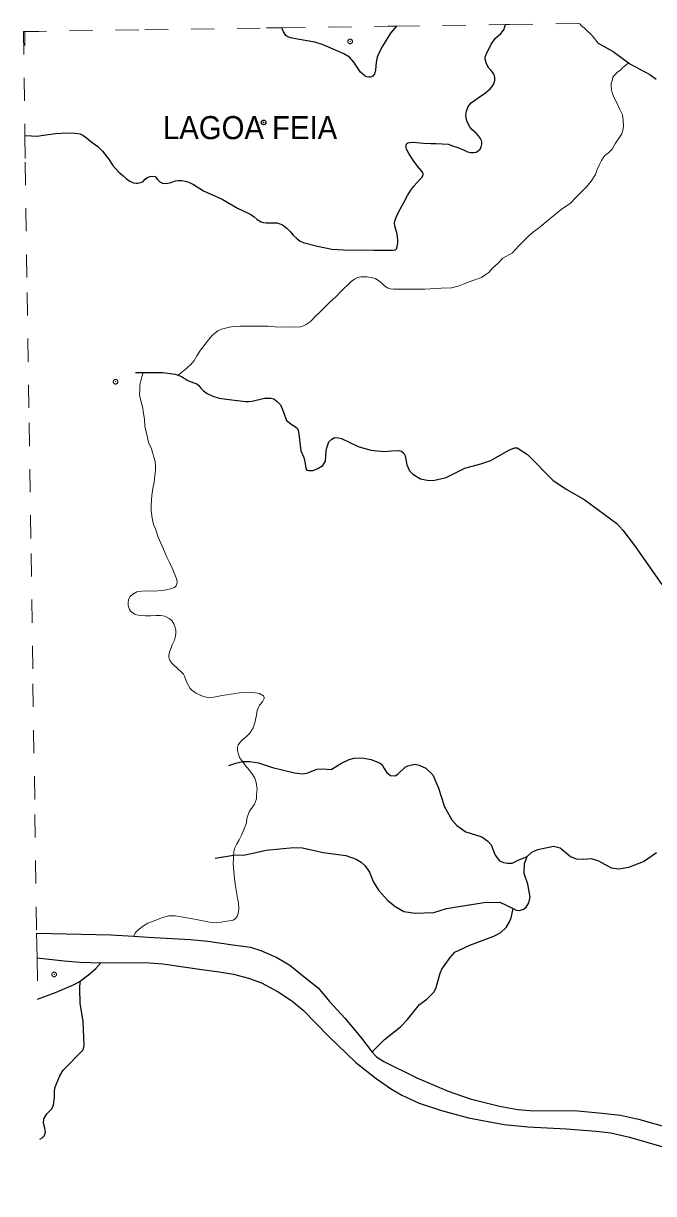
# Model space of a CAD drawing. Extents: x 267.7 to 296, y 7537.7 to 7565.8.
# Drawn here: x 267.7 to 270.43, y 7560.4 to 7565.47 of the extents above; entities that cross this region are included whole.
import ezdxf
from ezdxf.enums import TextEntityAlignment as Align

# ---------------------------------------------------------------- set-up
doc = ezdxf.new("R2010")
doc.units = 0
doc.header["$LTSCALE"] = 0.04
doc.header["$PDMODE"] = 32
doc.header["$PDSIZE"] = 0.02
doc.linetypes.add('SHORT_DASHED', pattern=[2.7, 1.5, -1.2])
for name, color, linetype, lineweight in [('1', 7, 'Continuous', 25), ('2', 7, 'Continuous', 25), ('21', 7, 'SHORT_DASHED', 13), ('62', 7, 'SHORT_DASHED', 13), ('63', 7, 'Continuous', 13), ('7', 7, 'Continuous', 25)]:
    doc.layers.add(name, color=color, linetype=linetype, lineweight=lineweight)
doc.layers.add('61', color=7, linetype='Continuous')

msp = doc.modelspace()

# ---------------------------------------------------------------- linework, layer by layer
at = {"layer": '1'}
for points in [[(267.7577, 7561.5276), (268.0791, 7561.5208), (268.1794, 7561.5143)], [(268.1794, 7561.5143), (268.2414, 7561.5102), (268.4249, 7561.4996), (268.5002, 7561.4928), (268.6084, 7561.4764), (268.6847, 7561.4667), (268.7301, 7561.4523), (268.7987, 7561.4223), (268.8557, 7561.3885), (268.9252, 7561.3325), (268.9784, 7561.2909), (269.0276, 7561.2311), (269.0952, 7561.1586), (269.1657, 7561.0727), (269.2121, 7561.0128)], [(267.7593, 7561.4209), (267.8767, 7561.4075), (267.9457, 7561.4017), (268.0364, 7561.3992)], [(268.0364, 7561.3992), (268.227, 7561.4), (268.3044, 7561.395), (268.4741, 7561.3709), (268.5489, 7561.3596), (268.6114, 7561.3501), (268.6763, 7561.3326), (268.7329, 7561.3118), (268.8045, 7561.2735), (268.8636, 7561.2344), (268.9126, 7561.1937), (269.0225, 7561.0813), (269.1415, 7560.9682), (269.2297, 7560.8983), (269.2921, 7560.855), (269.3404, 7560.8267), (269.4161, 7560.7917), (269.5134, 7560.7601), (269.6291, 7560.7285), (269.7847, 7560.6985), (269.8871, 7560.6894), (270.0543, 7560.6802), (270.1825, 7560.6694), (270.2474, 7560.6636), (270.3281, 7560.6436), (270.6385, 7560.5546)], [(269.2121, 7561.0128), (269.2305, 7560.9925), (269.2633, 7560.9712), (269.4053, 7560.9017), (269.5415, 7560.8437), (269.6371, 7560.8099), (269.7646, 7560.778), (269.8438, 7560.7636), (269.9134, 7560.7578), (270.0882, 7560.7597), (270.2099, 7560.7481), (270.2891, 7560.7394), (270.3664, 7560.722), (270.5103, 7560.6815), (270.9372, 7560.5636), (271.1913, 7560.4931), (271.4501, 7560.4207), (271.787, 7560.3318)]]:
    msp.add_lwpolyline(points, dxfattribs=at)
at = {"layer": '2'}
for points in [[(269.3177, 7565.456), (269.2917, 7565.4246), (269.2794, 7565.4072), (269.257, 7565.3684), (269.2417, 7565.3388), (269.2345, 7565.321), (269.2315, 7565.3072), (269.2284, 7565.2847), (269.2264, 7565.2643), (269.2218, 7565.2485), (269.2156, 7565.2393), (269.2085, 7565.2362), (269.2039, 7565.2342), (269.1978, 7565.2342), (269.1886, 7565.2367), (269.1825, 7565.2398), (269.162, 7565.2566), (269.1442, 7565.2827), (269.1329, 7565.3), (269.1136, 7565.321), (269.0891, 7565.3363), (269.0436, 7565.3567), (269.0002, 7565.3751), (268.9635, 7565.3863), (268.8885, 7565.3991), (268.8583, 7565.4057), (268.8466, 7565.4093), (268.8374, 7565.4159), (268.8272, 7565.4312), (268.8231, 7565.4414), (268.8221, 7565.4488)], [(269.3601, 7564.9361), (269.3601, 7564.9422), (269.3631, 7564.9468), (269.3672, 7564.9504), (269.3734, 7564.9524), (269.3897, 7564.9529), (269.4341, 7564.9489), (269.4663, 7564.9468), (269.4897, 7564.9478), (269.5423, 7564.9443), (269.5607, 7564.9381), (269.5831, 7564.93), (269.6112, 7564.9182), (269.626, 7564.9111), (269.6403, 7564.9085), (269.6531, 7564.9085), (269.6633, 7564.9101), (269.672, 7564.9157), (269.6801, 7564.9233), (269.6847, 7564.9336), (269.6878, 7564.9443), (269.6878, 7564.9545), (269.6857, 7564.9611), (269.6817, 7564.9698), (269.6725, 7564.9805), (269.6628, 7564.9917), (269.6444, 7565.0081), (269.6352, 7565.0198), (269.6245, 7565.0418), (269.6194, 7565.0566), (269.6178, 7565.0709), (269.6204, 7565.0872), (269.6286, 7565.1076), (269.6418, 7565.1234), (269.6714, 7565.1454), (269.7031, 7565.1668), (269.724, 7565.1847), (269.7327, 7565.1949), (269.7393, 7565.2061), (269.7434, 7565.2209), (269.7434, 7565.2316), (269.7424, 7565.2413), (269.7393, 7565.248), (269.7347, 7565.2556), (269.7281, 7565.2633), (269.7184, 7565.274), (269.7082, 7565.2919), (269.7046, 7565.3021), (269.7021, 7565.3133), (269.7026, 7565.321), (269.7067, 7565.3332), (269.7281, 7565.3771), (269.7465, 7565.4031), (269.7577, 7565.4144), (269.7694, 7565.4236), (269.7776, 7565.4327), (269.7837, 7565.443), (269.7863, 7565.4491), (269.7898, 7565.4629)], [(267.7068, 7564.9825), (267.7349, 7564.98), (267.7614, 7564.979), (267.7773, 7564.9815), (267.8401, 7564.9907), (267.8896, 7564.9938), (267.9243, 7564.9923), (267.9457, 7564.9892), (267.9544, 7564.9856), (267.9666, 7564.978), (267.9983, 7564.9519), (268.0228, 7564.9341), (268.0427, 7564.9136), (268.0697, 7564.8805), (268.0881, 7564.8529), (268.1121, 7564.8253), (268.1325, 7564.8075), (268.1468, 7564.7947), (268.1621, 7564.7845), (268.178, 7564.7774), (268.1897, 7564.7753), (268.1968, 7564.7753), (268.2091, 7564.7784), (268.2198, 7564.7835), (268.228, 7564.7927), (268.2372, 7564.7998), (268.2494, 7564.8044), (268.2627, 7564.8059), (268.2714, 7564.8039), (268.276, 7564.7993), (268.2821, 7564.7917), (268.2913, 7564.782), (268.3035, 7564.7758), (268.3158, 7564.7743), (268.327, 7564.7753), (268.3357, 7564.7774), (268.3438, 7564.7804), (268.3602, 7564.7855), (268.3719, 7564.7871), (268.3867, 7564.7866), (268.402, 7564.7845), (268.4168, 7564.7794), (268.4372, 7564.7702), (268.4817, 7564.7427), (268.5613, 7564.7059), (268.6281, 7564.6681), (268.6746, 7564.6462), (268.6858, 7564.6395), (268.7006, 7564.6293), (268.7134, 7564.6186), (268.7312, 7564.6079), (268.7409, 7564.6054), (268.7527, 7564.6038), (268.767, 7564.6038), (268.7996, 7564.6033), (268.8119, 7564.5997), (268.8231, 7564.5946), (268.8441, 7564.5788), (268.8578, 7564.5645), (268.8696, 7564.5512), (268.8869, 7564.5349), (268.9002, 7564.5252), (268.9135, 7564.5186), (268.9747, 7564.5028), (269.038, 7564.49), (269.088, 7564.4869), (269.2187, 7564.4859), (269.3029, 7564.4854), (269.3116, 7564.4864), (269.3152, 7564.488), (269.3177, 7564.492), (269.3203, 7564.5012), (269.3233, 7564.5155), (269.3233, 7564.5267), (269.3213, 7564.5451), (269.3187, 7564.5615), (269.3141, 7564.5757), (269.3101, 7564.5911), (269.309, 7564.6028), (269.3111, 7564.6105), (269.3152, 7564.6242), (269.3259, 7564.6503), (269.3494, 7564.6916), (269.3647, 7564.7222), (269.3795, 7564.7452), (269.3933, 7564.7631), (269.407, 7564.7784), (269.4203, 7564.7927), (269.4285, 7564.8019), (269.4321, 7564.8085), (269.4336, 7564.8131), (269.4336, 7564.8172), (269.4321, 7564.8202), (269.428, 7564.8274), (269.4091, 7564.8498)], [(269.4091, 7564.8498), (269.3892, 7564.8754), (269.3708, 7564.9039), (269.3616, 7564.9233), (269.3601, 7564.929), (269.3601, 7564.9361)]]:
    msp.add_lwpolyline(points, dxfattribs=at)
msp.add_point((268.7416, 7565.039), dxfattribs=at)
at = {"layer": '21'}
for points in [[(270.1922, 7565.3823), (270.1707, 7565.4091), (270.1597, 7565.4214), (270.1422, 7565.4362), (270.1306, 7565.4479), (270.1189, 7565.4569), (270.1112, 7565.4676)], [(270.2638, 7565.2442), (270.2767, 7565.2572), (270.289, 7565.2656), (270.2993, 7565.2766), (270.311, 7565.2856), (270.3235, 7565.2968)], [(268.3718, 7563.9436), (268.4005, 7563.9673), (268.4257, 7563.99), (268.4412, 7564.0081), (268.4528, 7564.0281), (268.4683, 7564.0527), (268.502, 7564.0966), (268.5175, 7564.1141), (268.5298, 7564.1257), (268.5433, 7564.1361), (268.5589, 7564.1438), (268.588, 7564.1509), (268.6086, 7564.1548), (268.6416, 7564.1561), (268.7037, 7564.1568), (268.7632, 7564.1561), (268.7916, 7564.1542), (268.8795, 7564.1522), (268.9015, 7564.1542), (268.9145, 7564.1574), (268.9261, 7564.1639), (268.9429, 7564.1749), (268.9532, 7564.1852), (268.9681, 7564.2007), (268.9817, 7564.2137), (268.9869, 7564.2188), (269.0289, 7564.2602), (269.056, 7564.2848), (269.0748, 7564.3048), (269.0877, 7564.3184), (269.1071, 7564.3352), (269.1213, 7564.3494), (269.1356, 7564.3604), (269.1485, 7564.3669), (269.1627, 7564.3701), (269.1905, 7564.3701), (269.2267, 7564.3624), (269.2416, 7564.3533), (269.2513, 7564.3449), (269.2668, 7564.3294), (269.281, 7564.3216), (269.2907, 7564.3184), (269.305, 7564.3171), (269.3651, 7564.3165), (269.4401, 7564.3165), (269.5112, 7564.321), (269.5565, 7564.3229), (269.5849, 7564.33), (269.6069, 7564.3378), (269.6437, 7564.3533), (269.6864, 7564.3675), (269.7052, 7564.3798), (269.7174, 7564.3895), (269.7336, 7564.407), (269.7562, 7564.4283), (269.7789, 7564.4516), (269.8209, 7564.4736), (269.8468, 7564.5027), (269.87, 7564.5266), (269.8914, 7564.5479), (269.9114, 7564.5647), (269.9315, 7564.5789), (269.9664, 7564.608), (269.9987, 7564.6339), (270.031, 7564.6623), (270.0724, 7564.6889), (270.0963, 7564.7154), (270.1209, 7564.7393), (270.1409, 7564.7593), (270.161, 7564.7845), (270.1804, 7564.8136), (270.1881, 7564.835), (270.1972, 7564.857), (270.2062, 7564.8744), (270.2133, 7564.886), (270.2224, 7564.8964), (270.2353, 7564.9061), (270.2521, 7564.9235), (270.2676, 7564.9488), (270.2799, 7564.9675), (270.2942, 7564.9895), (270.2993, 7565.0044), (270.3013, 7565.0231), (270.3, 7565.047), (270.2974, 7565.0723), (270.2864, 7565.0942), (270.2748, 7565.1214), (270.2625, 7565.1421), (270.2541, 7565.1628), (270.2495, 7565.1796), (270.2489, 7565.2003), (270.2489, 7565.2087), (270.2521, 7565.2184), (270.256, 7565.2345), (270.2638, 7565.2442)], [(268.2724, 7563.5322), (268.2731, 7563.5516), (268.2712, 7563.571), (268.266, 7563.5891), (268.2628, 7563.6001), (268.2556, 7563.6247), (268.2427, 7563.6531), (268.2388, 7563.6738), (268.2265, 7563.7229), (268.2253, 7563.7533), (268.2214, 7563.7785), (268.2175, 7563.8012), (268.2097, 7563.8335), (268.2039, 7563.8594), (268.2046, 7563.8788), (268.2052, 7563.8994), (268.2059, 7563.9085), (268.2136, 7563.9363), (268.2188, 7563.9557)], [(268.2556, 7563.4042), (268.2576, 7563.4236), (268.2608, 7563.4533), (268.2666, 7563.4805), (268.2699, 7563.5096), (268.2724, 7563.5322)], [(268.65, 7562.2712), (268.6377, 7562.2889), (268.6306, 7562.307), (268.6287, 7562.3193), (268.6287, 7562.3316), (268.6319, 7562.3432), (268.6416, 7562.3562), (268.6539, 7562.3691), (268.6681, 7562.3794), (268.6817, 7562.3937), (268.6959, 7562.4163), (268.7037, 7562.4383), (268.7114, 7562.4712), (268.714, 7562.4926), (268.7237, 7562.5152), (268.7367, 7562.5288), (268.7444, 7562.5437), (268.7444, 7562.5482), (268.7412, 7562.5559), (268.7237, 7562.565), (268.7147, 7562.5676), (268.694, 7562.5702), (268.6642, 7562.5708), (268.6364, 7562.5682), (268.5621, 7562.5566), (268.5265, 7562.5501), (268.5065, 7562.5475), (268.4865, 7562.5514), (268.469, 7562.5566), (268.449, 7562.5669), (268.438, 7562.574), (268.4296, 7562.5818), (268.4237, 7562.587), (268.4095, 7562.6109), (268.405, 7562.6245), (268.3985, 7562.6406), (268.394, 7562.649), (268.3869, 7562.6568), (268.3675, 7562.6749), (268.3526, 7562.6878), (268.3423, 7562.6988), (268.3352, 7562.7092), (268.33, 7562.7208), (268.33, 7562.7324), (268.3352, 7562.7493), (268.3403, 7562.7635), (268.3455, 7562.7758), (268.3546, 7562.7971), (268.3591, 7562.8139), (268.361, 7562.8262), (268.3617, 7562.8398), (268.3584, 7562.8514), (268.3526, 7562.8676), (268.3442, 7562.8812), (268.3319, 7562.8908), (268.3132, 7562.8999), (268.2951, 7562.9031), (268.2744, 7562.9038), (268.2518, 7562.9025), (268.2291, 7562.9025), (268.2123, 7562.9038), (268.1981, 7562.9051), (268.1852, 7562.9077), (268.1768, 7562.9128), (268.1645, 7562.9219), (268.1606, 7562.9296), (268.1548, 7562.9471), (268.1548, 7562.9581), (268.1561, 7562.9723), (268.1638, 7562.9859), (268.1742, 7562.9956), (268.1923, 7563.0053), (268.2136, 7563.0092), (268.2362, 7563.0098), (268.2653, 7563.0092), (268.3015, 7563.0118), (268.3203, 7563.015), (268.3377, 7563.0189), (268.3546, 7563.0247), (268.3623, 7563.0324), (268.3675, 7563.0454), (268.3655, 7563.0596), (268.3571, 7563.0809), (268.3455, 7563.1081), (268.3339, 7563.1327), (268.3222, 7563.1566), (268.308, 7563.1908), (268.2847, 7563.2419), (268.2724, 7563.2794), (268.264, 7563.2975), (268.2582, 7563.3253), (268.255, 7563.346), (268.2543, 7563.3583), (268.2537, 7563.3796), (268.2556, 7563.4042)], [(268.6115, 7561.8651), (268.6125, 7561.8797), (268.6171, 7561.8971), (268.6248, 7561.9152), (268.6352, 7561.932), (268.6461, 7561.9521), (268.6578, 7561.9799), (268.6675, 7562.0057), (268.6694, 7562.0245), (268.6746, 7562.0413), (268.6804, 7562.0555), (268.692, 7562.0717), (268.7024, 7562.0859), (268.7102, 7562.1092), (268.7114, 7562.1279), (268.7134, 7562.1506), (268.7089, 7562.1803), (268.7037, 7562.1991), (268.6946, 7562.2139), (268.6804, 7562.2314), (268.6727, 7562.2424), (268.6642, 7562.2514), (268.65, 7562.2712)], [(268.1794, 7561.5143), (268.1865, 7561.5312), (268.202, 7561.5454), (268.2214, 7561.5596), (268.2401, 7561.5713), (268.255, 7561.5771), (268.2789, 7561.5855), (268.2996, 7561.5933), (268.3145, 7561.5984), (268.3306, 7561.6023), (268.3591, 7561.6023), (268.3752, 7561.6004), (268.4173, 7561.5926), (268.4496, 7561.5868), (268.5143, 7561.5745), (268.5356, 7561.5719), (268.5582, 7561.5752), (268.5724, 7561.5777), (268.6099, 7561.5836), (268.6196, 7561.5907), (268.6274, 7561.6004), (268.6319, 7561.6127), (268.6339, 7561.6327), (268.6332, 7561.6586), (268.628, 7561.6786), (268.6242, 7561.7045), (268.6196, 7561.731), (268.6158, 7561.7639), (268.6119, 7561.795), (268.6099, 7561.8273), (268.6106, 7561.8512), (268.6115, 7561.8651)]]:
    msp.add_lwpolyline(points, dxfattribs=at)
for p in [(269.1168, 7565.3895), (268.0998, 7563.9157), (267.8337, 7561.3487)]:
    msp.add_point(p, dxfattribs=at)
at = {"layer": '62'}
for p, q in [((269.3177, 7565.456), (269.7898, 7565.4629)), ((267.7002, 7565.4324), (267.7068, 7564.9825)), ((267.7593, 7561.4209), (267.762, 7561.2411))]:
    msp.add_line(p, q, dxfattribs=at)
for points in [[(267.7002, 7565.4324), (268.2272, 7565.4401), (268.7541, 7565.4478), (268.8221, 7565.4488)], [(268.8221, 7565.4488), (269.2811, 7565.4555), (269.2887, 7565.4556), (269.3177, 7565.456)], [(269.7898, 7565.4629), (269.808, 7565.4632), (270.1112, 7565.4676)], [(267.7068, 7564.9825), (267.7085, 7564.8673), (267.7168, 7564.3023), (267.7252, 7563.7372), (267.7335, 7563.1722), (267.7418, 7562.6071), (267.7501, 7562.0421), (267.7577, 7561.5276)], [(267.7577, 7561.5276), (267.7585, 7561.477), (267.7593, 7561.4209)]]:
    msp.add_lwpolyline(points, dxfattribs=at)
at = {"layer": '63'}
msp.add_lwpolyline([(267.7674, 7565.432), (267.7058, 7565.432), (267.7058, 7565.3713)], dxfattribs=at)
at = {"layer": '7'}
for p, q in [((268.1859, 7563.9557), (268.2188, 7563.9557)), ((268.532, 7561.8531), (268.6115, 7561.8651))]:
    msp.add_line(p, q, dxfattribs=at)
for points in [[(270.1922, 7565.3823), (270.2571, 7565.3453), (270.3235, 7565.2968)], [(270.3235, 7565.2968), (270.3293, 7565.2926), (270.4159, 7565.2456), (270.4429, 7565.2259)], [(268.2188, 7563.9557), (268.3042, 7563.9557), (268.3585, 7563.9484), (268.3718, 7563.9436)], [(268.3718, 7563.9436), (268.3852, 7563.9389), (268.4127, 7563.9213), (268.4395, 7563.911), (268.4517, 7563.9066), (268.461, 7563.8994), (268.4692, 7563.8882), (268.4815, 7563.8769), (268.4969, 7563.8654), (268.5213, 7563.8526), (268.5484, 7563.8448), (268.5808, 7563.8407), (268.6625, 7563.8305), (268.6765, 7563.8307), (268.692, 7563.8321), (268.7459, 7563.844), (268.773, 7563.8448), (268.7855, 7563.8417), (268.8001, 7563.8296), (268.8141, 7563.8153), (268.8239, 7563.7949), (268.8415, 7563.7478), (268.8653, 7563.7294), (268.8797, 7563.7209), (268.8887, 7563.7139), (268.889, 7563.7137), (268.8926, 7563.7002), (268.9023, 7563.6162), (268.9153, 7563.5876), (268.9222, 7563.5615), (268.9239, 7563.5402), (268.929, 7563.533), (268.9383, 7563.531), (268.9547, 7563.532), (268.9737, 7563.5383), (268.9989, 7563.553), (269.0092, 7563.5723), (269.0124, 7563.617), (269.0161, 7563.6293), (269.0238, 7563.6553), (269.0368, 7563.6675), (269.0491, 7563.6747), (269.0659, 7563.6731), (269.0789, 7563.6695), (269.1515, 7563.6358), (269.2067, 7563.6191), (269.2635, 7563.6143), (269.2962, 7563.6161), (269.3295, 7563.618), (269.3396, 7563.6151), (269.3498, 7563.6069), (269.355, 7563.5946), (269.3622, 7563.5556), (269.3734, 7563.5302), (269.3886, 7563.515), (269.4216, 7563.4959), (269.4507, 7563.4889), (269.4772, 7563.4882), (269.5323, 7563.5008), (269.6141, 7563.5408), (269.6836, 7563.5607), (269.727, 7563.575), (269.8044, 7563.62), (269.8295, 7563.6293), (269.8407, 7563.6297), (269.8851, 7563.6009), (269.9952, 7563.49), (270.0537, 7563.4512), (270.1268, 7563.4082), (270.1356, 7563.403), (270.2724, 7563.3014), (270.299, 7563.2723), (270.3497, 7563.2064), (270.4684, 7563.0369)], [(268.5903, 7562.2535), (268.6211, 7562.2633), (268.65, 7562.2712)], [(268.65, 7562.2712), (268.6824, 7562.2712), (268.72, 7562.2657), (268.7794, 7562.2445), (268.8751, 7562.2214), (268.9122, 7562.217), (268.9326, 7562.2215), (268.9719, 7562.2373), (268.9968, 7562.24), (269.0344, 7562.2362), (269.0792, 7562.264), (269.1126, 7562.2799), (269.1347, 7562.286), (269.1708, 7562.2872), (269.1835, 7562.2846), (269.2079, 7562.2795), (269.2467, 7562.2634), (269.255, 7562.2568), (269.264, 7562.2406), (269.2749, 7562.2254), (269.2913, 7562.2106), (269.3121, 7562.2083), (269.3239, 7562.2156), (269.3548, 7562.2459), (269.3668, 7562.2529), (269.3978, 7562.2591), (269.4152, 7562.2551), (269.4449, 7562.2425), (269.4746, 7562.2126), (269.5006, 7562.1527), (269.5072, 7562.1325), (269.5259, 7562.0749), (269.558, 7562.0187), (269.5785, 7561.9933), (269.6187, 7561.9665), (269.6875, 7561.9441), (269.7133, 7561.9263), (269.7277, 7561.91), (269.7456, 7561.8655), (269.7637, 7561.841), (269.7809, 7561.8333), (269.7994, 7561.8302), (269.8189, 7561.8312), (269.8456, 7561.8435), (269.8839, 7561.8603)], [(268.6115, 7561.8651), (268.6214, 7561.8666), (268.6555, 7561.8647), (268.752, 7561.8866), (268.8712, 7561.8987), (268.9095, 7561.8977), (268.9807, 7561.8811), (268.9992, 7561.8768), (269.0983, 7561.8636), (269.1433, 7561.8483), (269.1643, 7561.8353), (269.1816, 7561.8188), (269.2001, 7561.7913), (269.2166, 7561.7519), (269.239, 7561.7145), (269.278, 7561.6704), (269.3118, 7561.6437), (269.3182, 7561.64), (269.3497, 7561.6215), (269.399, 7561.6146), (269.4797, 7561.6169), (269.5341, 7561.6347), (269.6967, 7561.6608), (269.7649, 7561.6614), (269.8228, 7561.6343)], [(269.8839, 7561.8603), (269.904, 7561.8777), (269.9305, 7561.8894), (269.9987, 7561.9049), (270.0274, 7561.8978), (270.0715, 7561.86), (270.0971, 7561.8497), (270.1303, 7561.8475), (270.1615, 7561.8514), (270.1937, 7561.8402), (270.2488, 7561.8102), (270.2817, 7561.8062), (270.3244, 7561.8137), (270.3884, 7561.8381), (270.445, 7561.8765)], [(269.8228, 7561.6343), (269.837, 7561.6276), (269.8507, 7561.6259), (269.8681, 7561.6315), (269.8793, 7561.6404), (269.8915, 7561.6585), (269.8965, 7561.6831), (269.887, 7561.7403), (269.8711, 7561.7859), (269.8723, 7561.8292), (269.8795, 7561.8487), (269.8839, 7561.8603)], [(269.2121, 7561.0128), (269.2256, 7561.0273), (269.2658, 7561.0668), (269.3343, 7561.1224), (269.3649, 7561.1539), (269.4174, 7561.2191), (269.4496, 7561.2424), (269.4803, 7561.274), (269.4889, 7561.2925), (269.5063, 7561.3538), (269.5147, 7561.3711), (269.5504, 7561.4223), (269.5708, 7561.4449), (269.6352, 7561.475), (269.7394, 7561.5144), (269.7703, 7561.5305), (269.7934, 7561.5528), (269.8078, 7561.5761), (269.8149, 7561.5946), (269.8228, 7561.6343)], [(267.9457, 7561.3193), (267.9721, 7561.3393), (267.9832, 7561.3476), (268.0148, 7561.3742), (268.0364, 7561.3992)], [(267.762, 7561.2411), (267.84, 7561.2711), (267.9199, 7561.306), (267.9457, 7561.3193)], [(267.7709, 7560.6355), (267.7815, 7560.6416), (267.7918, 7560.6519), (267.7959, 7560.6662), (267.7928, 7560.6827), (267.7878, 7560.705), (267.7892, 7560.7237), (267.8018, 7560.7453), (267.8232, 7560.7665), (267.8308, 7560.7822), (267.8349, 7560.8192), (267.8349, 7560.8377), (267.8369, 7560.8572), (267.8583, 7560.9094), (267.8732, 7560.9339), (267.9589, 7561.0228), (267.9642, 7561.0415), (267.9588, 7561.1451), (267.9459, 7561.2238), (267.9449, 7561.2864), (267.9457, 7561.3193)]]:
    msp.add_lwpolyline(points, dxfattribs=at)

# ---------------------------------------------------------------- texts
at = {"layer": '61', "width": 0.95}
msp.add_text('LAGOA FEIA', height=0.1, dxfattribs=at).set_placement((268.683, 7564.9663), align=Align.CENTER)

doc.saveas('drawing.dxf')
